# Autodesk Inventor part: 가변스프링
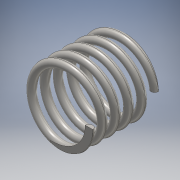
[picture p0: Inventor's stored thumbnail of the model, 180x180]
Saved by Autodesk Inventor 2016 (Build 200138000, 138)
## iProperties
Created: 2019-11
Part Number: 가변스프링
Material: 스테인레스 스틸
Document SubType Name: Modeling
Designer: user
Density: 8 g/cm^3
Appearance: 반연마
Mass: 6.55763 g
Surface Area: 16.7052 cm^2
Volume: 0.819704 cm^3
Author: user
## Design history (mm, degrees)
sketch "스케치1"
  geometry: L1 (0, 0)-(8.5, 0); L2 (8.5, 0)-(8.5, 17.5); L3 (8.5, 17.5)-(0, 17.5); L4 (0, 17.5)-(0, 0); C1 r 1 at (8.5, 0)
  constraints: 8 end point, 2 parallel, 1 centre point, 1 coincident, 1 horizontal, 1 perpendicular
  dimensions: "d1" = 17 diameter of L2 L4; "d2" = 17.5 distance between parallel lines of L1 L3 (derived); "d3" = 2 diameter of C1
feature "코일1" sketch "스케치1" pitch "d4" = 10; turns "d6" = 5; dims "d5" = 17.5 (= d2), "d7" = 0, angle "d8" = 90 deg, angle "d9" = 90 deg, "d10" = 0, "d11" = 0
sketch "스케치2"
  geometry: L1 (0, 13.879)-(17.5, 13.879); L2 (17.5, 13.879)-(17.5, -13.879); L3 (17.5, -13.879)-(0, -13.879); L4 (0, -13.879)-(0, 13.879); 2 further points
  constraints: 8 end point, 2 parallel, 1 coincident, 1 horizontal, 1 midpoint, 1 perpendicular
  dimensions: "d12" = 17.5 distance between parallel lines of L4 L2 (= d2); "d13" = 27.7574 distance between parallel lines of L1 L3
extrude "돌출1" sketch "스케치2" stored distance "d14" = 50; taper "d15" = 0 deg
node "솔리드1"
